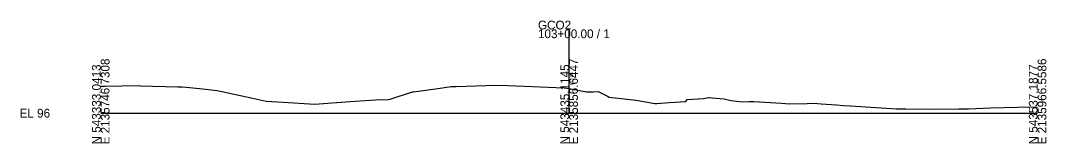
# Model space of a CAD drawing. Extents: x -14327 to 8886, y -10 to 39048.
# Drawn here: x 3974.3 to 4302.8, y 25990.3 to 26029.6 of the extents above; entities that cross this region are included whole.
import ezdxf

# ---------------------------------------------------------------- set-up
doc = ezdxf.new("R2010")
doc.units = 0
for name, color, linetype in [('RD_GPK_XS_Cell', 7, 'Continuous'), ('RD_XS_ExGround', 7, 'Continuous'), ('RD_XS_TX_Elev_EX', 7, 'Continuous')]:
    doc.layers.add(name, color=color, linetype=linetype)

msp = doc.modelspace()

# ---------------------------------------------------------------- linework, layer by layer
at = {"layer": 'RD_GPK_XS_Cell'}
for p, q in [((4150, 26000), (4150, 26026.81)), ((4000, 26000), (4150, 26000)), ((4150, 26000), (4300, 26000))]:
    msp.add_line(p, q, dxfattribs=at)
at = {"layer": 'RD_XS_ExGround'}
for p, q in [((4000, 26008.6), (4000.18, 26008.6)), ((4000.18, 26008.6), (4001.43, 26008.62)), ((4001.43, 26008.62), (4012.1, 26008.82)), ((4012.1, 26008.82), (4012.78, 26008.8)), ((4012.78, 26008.8), (4024.63, 26008.45)), ((4024.63, 26008.45), (4026.12, 26008.41)), ((4026.12, 26008.41), (4027.31, 26008.37)), ((4027.31, 26008.37), (4031.6, 26007.93)), ((4031.6, 26007.93), (4037.32, 26007.28)), ((4037.32, 26007.28), (4038.8, 26006.95)), ((4038.8, 26006.95), (4048.18, 26004.87)), ((4092.69, 26004.49), (4099.86, 26006.78)), ((4099.86, 26006.78), (4100.17, 26006.87)), ((4100.17, 26006.87), (4107.14, 26007.82)), ((4107.14, 26007.82), (4111.57, 26008.48)), ((4111.57, 26008.48), (4112.18, 26008.5)), ((4112.18, 26008.5), (4113.84, 26008.5)), ((4113.84, 26008.5), (4123.27, 26008.84)), ((4123.27, 26008.84), (4126.38, 26008.94)), ((4126.38, 26008.94), (4130.27, 26008.82)), ((4130.27, 26008.82), (4138.29, 26008.56)), ((4138.29, 26008.56), (4145.77, 26008.25)), ((4145.77, 26008.25), (4148.41, 26008.13)), ((4148.41, 26008.13), (4150, 26007.85)), ((4150, 26007.85), (4150.58, 26007.75)), ((4150.58, 26007.75), (4155.59, 26006.84)), ((4155.59, 26006.84), (4157.67, 26006.83)), ((4157.67, 26006.83), (4159.23, 26006.89)), ((4159.23, 26006.89), (4162.29, 26005.4)), ((4048.18, 26004.87), (4053.01, 26003.82)), ((4053.01, 26003.82), (4058.38, 26003.49)), ((4058.38, 26003.49), (4068.59, 26002.9)), ((4068.59, 26002.9), (4079.73, 26003.7)), ((4079.73, 26003.7), (4089.74, 26004.33)), ((4089.74, 26004.33), (4091.47, 26004.3)), ((4091.47, 26004.3), (4092.69, 26004.49)), ((4162.29, 26005.4), (4162.84, 26005.13)), ((4162.84, 26005.13), (4163.74, 26005.02)), ((4163.74, 26005.02), (4171.43, 26004.14)), ((4171.43, 26004.14), (4177.48, 26003.05)), ((4178.02, 26003.09), (4182.04, 26003.47)), ((4182.04, 26003.47), (4187.36, 26003.79)), ((4187.36, 26003.79), (4187.81, 26004.34)), ((4187.81, 26004.34), (4192.99, 26004.73)), ((4192.99, 26004.73), (4194.57, 26005.05)), ((4194.57, 26005.05), (4194.93, 26004.98)), ((4194.93, 26004.98), (4195.79, 26004.94)), ((4195.79, 26004.94), (4199.66, 26004.58)), ((4199.66, 26004.58), (4201.74, 26004.08)), ((4201.74, 26004.08), (4204.54, 26003.78)), ((4204.54, 26003.78), (4205.38, 26003.66)), ((4205.38, 26003.66), (4207.5, 26003.75)), ((4207.5, 26003.75), (4209.08, 26003.69)), ((4209.08, 26003.69), (4218.01, 26003.21)), ((4177.48, 26003.05), (4178.02, 26003.09)), ((4218.01, 26003.21), (4220.56, 26003.03)), ((4220.56, 26003.03), (4226.23, 26003.15)), ((4226.23, 26003.15), (4228.31, 26003.22)), ((4228.31, 26003.22), (4230.67, 26003.04)), ((4230.67, 26003.04), (4235.64, 26002.7)), ((4235.64, 26002.7), (4237.8, 26002.47)), ((4237.8, 26002.47), (4240.11, 26002.39)), ((4240.11, 26002.39), (4254.84, 26001.41)), ((4254.84, 26001.41), (4257.82, 26001.38)), ((4257.82, 26001.38), (4264.91, 26001.26)), ((4264.91, 26001.26), (4274.82, 26001.43)), ((4274.82, 26001.43), (4277.83, 26001.44)), ((4277.83, 26001.44), (4284.92, 26001.75)), ((4284.92, 26001.75), (4293.59, 26001.89)), ((4293.59, 26001.89), (4297.84, 26001.99)), ((4297.84, 26001.99), (4300, 26001.97))]:
    msp.add_line(p, q, dxfattribs=at)

# ---------------------------------------------------------------- texts
at = {"layer": 'RD_GPK_XS_Cell'}
for s, p in [('GCO2', (4140, 26026.81)), ('103+00.00 / 1', (4140, 26024.01)), ('EL 96', (3974, 25998.6))]:
    msp.add_text(s, height=2.8, dxfattribs=at).set_placement(p)
for s, p in [('E 2135746.7308', (4002.8, 25990)), ('E 2135856.6447', (4152.8, 25990)), ('E 2135966.5586', (4302.8, 25990)), ('N 543333.0413', (4000, 25990)), ('N 543435.1145', (4150, 25990)), ('N 543537.1877', (4300, 25990))]:
    msp.add_text(s, height=2.8, rotation=90, dxfattribs=at).set_placement(p)
at = {"layer": 'RD_XS_TX_Elev_EX'}
msp.add_text('103.85', height=1, rotation=90, dxfattribs=at).set_placement((4151.25, 26008.85))

doc.saveas('drawing.dxf')
